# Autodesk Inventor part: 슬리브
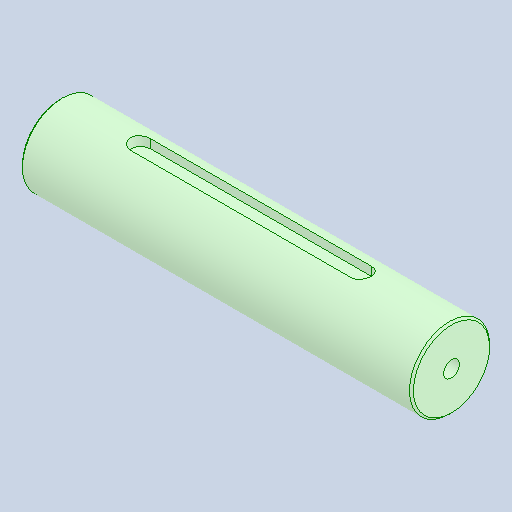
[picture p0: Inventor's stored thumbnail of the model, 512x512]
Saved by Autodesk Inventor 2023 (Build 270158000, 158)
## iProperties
Created: 2024-07
Part Number: 슬리브
Material: 강철, 탄소
Document SubType Name: Modeling
Designer: home
Density: 7.85 g/cm^3
Appearance: 기본값
Author: jhkim
Sending System: Autodesk Inventor 2025
Preprocessor: ST-DEVELOPER v20
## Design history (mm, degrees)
feature "솔리드1"
node "솔리드2"
